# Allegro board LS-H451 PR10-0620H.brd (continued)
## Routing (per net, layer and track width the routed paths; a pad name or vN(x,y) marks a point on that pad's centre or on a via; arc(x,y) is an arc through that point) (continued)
LINE1-L_C: length 8.1
  TOP w0.305: v1(25.06,16.39) 24.98,16.39 24.34,17.02 RA202.1
  IN2 w0.305: v1(25.06,16.39) 21.74,13.06 v1(20.13,13.06)
  BOTTOM w0.305: CA165.2 v1(20.13,13.06)
LINE1-L_R: length 11
  TOP w0.127: RA32.1 24.02,18.04 v3(24.02,18.92)
  TOP w0.305: v1(25.06,17.02) 25.06,17.3 24.51,17.85 RA32.1
  IN2 w0.305: v1(18.93,13.06) 19.65,13.79 21.4,13.79 24.64,17.02 v1(25.06,17.02)
  BOTTOM w0.305: CA166.2 18.89,13.02 v1(18.93,13.06)
LINE1_L: length 2.2
  TOP w0.203: v1(19.23,14.58) 18.99,14.82 UA7.18
  BOTTOM w0.305: CA165.1 20.12,13.79 19.33,14.58 v1(19.23,14.58)
LINE1_R: length 1.8
  TOP w0.203: v1(18.63,14.53) 18.63,14.97 18.59,15.01 UA7.17
  BOTTOM w0.305: CA166.1 18.63,14.04 v1(18.63,14.53)
LX_5VB: length 9.8
  IN2 w0.254: v1(9.34,75.98) 5.78,72.42 5.78,68.87 5.4,68.48 v1(5.4,68.47)
  BOTTOM w0.508: v1(5.4,68.47) 5.91,68.47 5.93,68.5 PR516.1
  vias: v3(8.5,77.22)
MIC_CAP:
  vias: v2(17.66,13.98)
POK: length 1.5
  BOTTOM w0.254: PR511.1 7.88,71.87 7.09,72.66 PU502.12
POWER_SW#_MB: length 60.1
  TOP w0.102: SW3.4 12.45,70.65 11.24,69.44 v1(11.24,67.39)
  IN1 w0.135: v1(11.24,67.39) 10.57,67.39 8,64.83 8,58.54 10.62,55.92 10.62,25.9 11,25.52 11,23.6 11.69,22.91 11.69,20.41 v1(11.51,20.23)
  BOTTOM w0.102: JIO1.7 15.59,19.55 14.86,20.28 14.44,20.28 13.55,19.39 11.57,19.39 11.51,19.45 v1(11.51,20.23)
PWM_FAN1: length 30
  TOP w0.102: v2(14.8,24.2) 14.75,24.25 v1(14.09,24.25)
  IN2 w0.135: v1(11.43,39.44) 12.51,38.36 12.51,25.83 v1(14.09,24.25)
  BOTTOM w0.102: v1(14.09,24.25) 14.23,24.11 15.69,24.11 JIO1.16 ; v1(11.43,39.44) 11.37,39.38 8.45,39.38 8.16,39.66 JFAN1.2 8.16,42.26 9.16,43.26 11.85,43.26 12.46,43.87 C124.1
RING2: length 25.4
  TOP w0.203: UA7.13 16.99,14.96 16.51,14.48 v1(16.51,14.42) v1(16.51,13.84)
  IN1 w1.016: 20.77,15.25 22.33,15.25 23.06,15.98 23.06,17.86 23.64,18.44 23.64,22.72 22.99,23.37 22.99,24.96 25.47,27.44 25.47,33.41 26.48,34.42 26.48,34.93
  vias: v1(27.55,35.31) v1(28.13,35.31)
RING2_R: length 16.4
  IN2 w1.016: JHP1.4 37.5,34.79 35.88,36.4 23.56,36.4
  BOTTOM w0.127: LA27.2 25.17,35.29 25.78,34.68 v2(25.78,34.17)
  vias: v1(20.62,36.58) v1(20.62,35.95)
SLEEVE: length 20.2
  TOP w0.203: UA7.14 17.39,14.82 17.11,14.55 v1(17.11,14.42) v1(17.11,13.84)
  IN1 w1.016: 21.09,13.85 22.55,13.85 24.2,15.5 24.2,17.38 24.78,17.97 24.78,24.66 26.61,26.49 26.61,29.15
  vias: v1(26.74,30.99) v1(26.74,30.3) v2(26.04,30.3)
SLEEVE_R: length 25.9
  IN2 w0.838: JHP1.1 37.5,25.79 36.46,24.75 28.83,24.75 28,25.58
  IN2 w1.016: 28,25.58 25.59,27.98 25.59,32.77 23.56,34.8 20.51,34.8 19.69,35.63
  vias: v1(18.67,36.65) v1(18.67,36.01) v1(18.67,34.74) v1(19.31,34.74) v1(23.37,33.28) v1(23.37,32.65) v3(22.86,33.03)
SPK_-OUT-L+: length 27.2
  TOP w0.203: v1(18.48,23.18) v1(18.48,22.6) 18.19,22.3 UA7.35
  IN1 w0.762: 17.78,21.66 17.09,20.96 14.66,20.96 13.72,20.02 13.72,17.43 11.97,15.68 11.97,10.78 12.26,10.48 12.26,8.18 13.01,7.44 17.28,7.44 18.48,6.23
  vias: v1(18.41,5.47) v1(18.99,5.47)
SPK_-OUT-L-: length 24.8
  TOP w0.203: UA7.36 17.79,21.53 v1(17.09,22.23) v1(17.09,23.37)
  IN1 w0.762: 14.16,21.72 12.83,20.39 12.83,17.8 11.08,16.05 11.08,10.41 11.37,10.12 11.37,7.82 12.64,6.55 16.7,6.55 17.09,6.17
  vias: v1(16.82,5.47) v1(17.4,5.47)
SPK_-OUT-R+: length 22.4
  TOP w0.203: v1(14.3,22.68) v1(14.91,22.68) 15.52,22.68 16.99,21.22 UA7.38
  IN2 w0.762: 13.88,21.7 13.87,21.68 13.87,17.58 11.97,15.68 11.97,10.76 12.26,10.47 12.26,8.18 13.2,7.25 14.42,7.25 15.5,6.17
  vias: v1(14.98,5.47) v1(15.56,5.47)
SPK_-OUT-R-: length 23.9
  TOP w0.203: UA7.37 17.39,21.29 16.41,22.27 v1(16.41,22.89) v1(16.41,23.48)
  IN2 w0.762: 15.31,23.44 13.91,23.44 12.98,22.51 12.98,17.95 11.08,16.05 11.08,10.39 11.37,10.1 11.37,7.82 12.89,6.29 13.02,6.29
  vias: v1(13.33,5.47) v1(13.91,5.47)
SPK_L+:
  vias: v1(18.93,8.97) v1(18.93,8.38)
SPK_L-:
  vias: v1(16.77,9.04) v1(16.77,8.46)
SPK_R+:
  vias: v1(15.5,9.04) v1(15.5,8.46)
SPK_R-:
  vias: v1(13.3,9.03) v1(13.3,8.45)
SPKR: length 26.1
  TOP w0.102: DA19.2 6.51,15.32 10.59,11.24 v2(10.59,10.42) v1(10.59,9.62)
  IN1 w0.135: v1(10.59,9.62) 10.25,9.97 10.25,15.72 9.93,16.05 9.93,16.72 10.93,17.72 10.93,19.06 10.23,19.75 10.23,20.79 v1(11.15,21.72)
  BOTTOM w0.102: v1(11.15,21.72) 11.2,21.72 11.67,21.24 11.67,21.11 11.78,21.01 14.26,21.01 14.38,20.89 15.13,20.89 15.46,20.55 JIO1.9
TACH_FAN1: length 26.3
  TOP w0.102: v1(9.16,39.82) 9.99,40.65 v1(11.5,40.65) ; v2(15.75,25.03) 15.62,24.89 v1(14.09,24.89)
  IN2 w0.135: v1(14.09,24.89) 13.21,25.77 13.21,38.93 v1(11.5,40.65)
  BOTTOM w0.102: v1(14.09,24.89) 14.47,24.51 14.47,24.45 14.57,24.34 15.29,24.34 15.49,24.55 JIO1.17 ; v1(11.5,40.65) 12.67,40.65 CE99.1 12.77,40.8 C123.1 ; JFAN1.3 v1(9.16,39.82)
USB3_CRX_DTX_N3: length 60.4
  TOP w0.102: v1(21.47,68.46) 21.28,68.27 20.96,68.27 20.65,67.96 20.65,66.25 22.86,64.04 22.86,63.74 22.68,63.55 22.31,63.55 22.18,63.68 EU1.9 EU1.1 20.54,63.68 20.41,63.55 18.33,63.55 v4(17.98,63.9) 17.64,64.24 14.91,64.24 v1(14.73,64.42)
  IN1 w0.135: v1(13.78,31.63) 13.65,31.5 12.95,31.5 12.28,32.17 12.28,38.34 13.02,39.08 13.02,41.73 12.28,42.47 12.28,60.23 15.56,63.51 15.56,64.01 15.25,64.33 14.83,64.33 v1(14.73,64.42)
  IN2 w0.135: v1(21.47,68.46) 21.59,68.33 25.91,68.33 26.59,69.01 27.05,69.01 27.18,69.15 JUSB1.5
  BOTTOM w0.102: JIO1.31 15.75,31.55 15.7,31.5 15.4,31.5 15.35,31.55 14.44,31.55 14.32,31.44 13.98,31.44 v1(13.78,31.63)
USB3_CRX_DTX_N4: length 33.1
  TOP w0.102: v1(13.66,45.56) 13.82,45.39 18.82,45.39 18.95,45.52 EU8.1 EU8.9 20.59,45.52 20.72,45.39 20.89,45.39 20.99,45.49 20.99,46.46 20.65,46.8 20.65,49.1 21.01,49.46 21.33,49.46 v1(21.47,49.6)
  IN1 w0.135: v1(13.66,45.56) 13.79,45.43 14.08,45.43 14.48,45.03 14.48,42.55 14.61,42.42 14.61,38.52 13.8,37.71 13.8,34.8 13.99,34.61 14.16,34.61 v1(14.29,34.74)
  IN2 w0.135: JUSB2.5 27.18,49.6 27.05,49.46 26.54,49.46 25.98,48.9 24.77,48.9 24.2,49.47 21.59,49.47 v1(21.47,49.6)
  BOTTOM w0.102: v1(14.29,34.74) 14.48,34.55 JIO1.37
USB3_CRX_DTX_P3: length 60.5
  TOP w0.102: v1(21.47,67.87) 21.32,68.02 21.06,68.02 20.9,67.86 20.9,66.35 23.1,64.14 23.1,63.63 22.78,63.31 22.28,63.31 22.16,63.18 EU1.8 EU1.2 20.54,63.18 20.41,63.31 18.22,63.31 17.53,64 14.89,64 v1(14.73,63.84)
  IN1 w0.135: v1(14.73,63.84) 14.9,64 15.12,64 15.24,63.88 15.24,63.64 11.96,60.36 11.96,42.33 12.7,41.59 12.7,39.21 11.96,38.47 11.96,32.04 12.82,31.18 13.65,31.18 v1(13.78,31.05)
  IN2 w0.135: JUSB1.6 27.18,68.55 27.05,68.69 26.72,68.69 26.05,68.01 21.6,68.01 v1(21.47,67.87)
  BOTTOM w0.102: JIO1.30 15.62,31.18 15.37,31.18 15.25,31.3 14.54,31.3 14.43,31.19 13.93,31.19 v1(13.78,31.05)
USB3_CRX_DTX_P4: length 33.3
  TOP w0.102: v1(21.47,49.02) 21.26,49.22 21.12,49.22 20.9,49 20.9,46.9 21.24,46.56 21.24,45.39 20.99,45.15 20.7,45.15 20.57,45.02 EU8.8 EU8.2 18.95,45.02 18.82,45.15 13.82,45.15 v1(13.66,44.98)
  IN1 w0.135: v1(13.66,44.98) 13.79,45.11 13.94,45.11 14.16,44.89 14.16,42.42 14.29,42.29 14.29,38.65 13.48,37.84 13.48,34.66 13.86,34.29 14.16,34.29 v1(14.29,34.16)
  IN2 w0.135: v1(21.47,49.02) 21.6,49.15 24.06,49.15 24.63,48.58 26.11,48.58 26.67,49.14 27.05,49.14 27.18,49 JUSB2.6
  BOTTOM w0.102: v1(14.29,34.16) 14.44,34.3 15.3,34.3 15.55,34.05 JIO1.36
USB3_CTX_C_DRX_N3: length 12.2
  TOP w0.102: CI143.2 17.75,62.05 v4(18.58,62.05) 20.41,62.05 20.54,62.18 EU1.4 EU1.7 22.4,62.18 22.52,62.05 22.88,62.05 v1(23.05,62.22)
  IN2 w0.135: JUSB1.8 27.18,63.17 27.03,63.02 26.86,63.02 26.03,63.85 24.44,63.85 23.54,62.95 23.54,62.22 23.38,62.05 23.22,62.05 v1(23.05,62.22)
USB3_CTX_C_DRX_N4: length 11
  TOP w0.102: CI141.2 17.92,43.85 18.4,43.85 18.45,43.89 18.82,43.89 18.95,44.02 EU8.4 EU8.7 20.89,44.02 21.01,43.89 21.28,43.89 v1(21.47,44.08)
  IN2 w0.135: v1(21.47,44.08) 21.6,43.94 22.3,43.94 22.5,44.14 26.18,44.14 26.87,43.46 27.05,43.46 27.18,43.6 JUSB2.8
USB3_CTX_C_DRX_P3: length 12.2
  TOP w0.102: v1(23.05,61.64) 22.88,61.81 22.52,61.81 22.4,61.68 EU1.6 EU1.5 20.54,61.68 20.41,61.81 v4(19.96,61.81) 17.84,61.81 CI142.2
  IN2 w0.135: JUSB1.9 27.18,62.58 27.06,62.7 26.73,62.7 25.9,63.53 24.58,63.53 23.87,62.82 23.87,62.08 23.51,61.73 23.14,61.73 v1(23.05,61.64)
USB3_CTX_C_DRX_P4: length 10.9
  TOP w0.102: CI140.2 17.92,43.6 18.51,43.6 18.55,43.65 18.82,43.65 18.95,43.52 EU8.5 EU8.6 20.91,43.52 21.04,43.65 21.31,43.65 v1(21.47,43.49)
  IN2 w0.135: JUSB2.9 27.18,43 27.05,43.14 26.73,43.14 26.05,43.82 22.63,43.82 22.43,43.62 21.6,43.62 v1(21.47,43.49)
USB3_CTX_DRX_N3: length 36.7
  TOP w0.102: v1(15.29,62.18) 15.46,62.01 16.76,62.01 CI143.1
  IN1 w0.135: v1(15.29,62.18) 15.42,62.05 15.94,62.05 16.26,61.73 16.26,61.09 13.04,57.88 13.04,42.85 13.79,42.1 13.79,38.77 13.04,38.02 13.04,33.08 13.29,32.83 13.65,32.83 v1(13.78,32.96)
  BOTTOM w0.102: v1(13.78,32.96) 13.95,32.8 15.14,32.8 15.39,33.05 JIO1.34
USB3_CTX_DRX_N4: length 12.8
  TOP w0.102: v1(14.99,44.01) 15.15,43.85 16.88,43.85 CI141.1
  IN1 w0.135: v1(14.99,44.01) 15.12,43.88 15.51,43.88 15.94,43.45 15.94,38.77 14.57,37.39 14.57,36.13 14.69,36.01 14.8,36.01 v1(14.99,36.2)
  BOTTOM w0.102: JIO1.40 15.64,35.94 15.25,35.94 v1(14.99,36.2)
USB3_CTX_DRX_P3: length 36.5
  TOP w0.102: CI142.1 16.76,61.76 15.46,61.76 v1(15.29,61.59)
  IN1 w0.135: v1(15.29,61.59) 15.42,61.73 15.81,61.73 15.94,61.59 15.94,61.23 12.72,58.01 12.72,42.71 13.47,41.97 13.47,38.9 12.72,38.16 12.72,32.95 13.16,32.51 13.65,32.51 v1(13.78,32.38)
  BOTTOM w0.102: JIO1.33 13.95,32.55 v1(13.78,32.38)
USB3_CTX_DRX_P4: length 12.8
  TOP w0.102: CI140.1 16.88,43.6 15.16,43.6 v1(14.99,43.43)
  IN1 w0.135: v1(14.99,43.43) 15.12,43.56 15.37,43.56 15.62,43.31 15.62,38.9 14.24,37.53 14.24,35.99 14.55,35.68 14.8,35.68 v1(14.99,35.49)
  BOTTOM w0.102: JIO1.39 15.75,35.55 15.6,35.69 15.19,35.69 v1(14.99,35.49)
USB20_N1_R: length 47.9
  IN1 w0.104: v1(14.42,66.54) 14.61,66.35 14.61,65.56 11.34,62.29 11.34,41.99 11.94,41.39 11.94,39.33 11.34,38.73 11.34,28.28 14.01,25.61 14.8,25.61 v1(14.9,25.51)
  BOTTOM w0.094: JIO1.19 15.75,25.55 15.66,25.63 15.03,25.63 v1(14.9,25.51) ; v1(14.42,66.54) 14.42,65.92 14.79,65.55 LU1.3
USB20_N1_R1: length 11.7
  IN2 w0.104: JUSB1.2 25.68,65.65 25.58,65.75 19.35,65.75 v1(19.12,65.53)
  BOTTOM w0.094: v1(19.12,65.53) 18.92,65.73 18.26,65.73 18.2,65.67 DI1.2 17.36,65.74 16.9,65.74 16.63,65.47 RU1.2
USB20_N2_R: length 24.5
  IN1 w0.104: v1(16.49,27.26) 16.31,27.44 16.05,27.44 15.56,27.93 15.56,37.17 16.45,38.06 16.45,46.28 15.64,47.09 14.62,47.09 v1(14.43,46.89)
  BOTTOM w0.094: JIO1.22 15.88,27.05 16.2,27.37 16.38,27.37 v1(16.49,27.26) ; v1(14.43,46.89) 14.63,47.09 15.06,47.09 15.22,46.94 LU2.3
USB20_N2_R1: length 13
  IN2 w0.104: v1(21.5,47.82) 21.69,48.01 22.26,48.01 24.08,46.2 25.58,46.2 25.68,46.1 JUSB2.2
  BOTTOM w0.094: v1(21.5,47.82) 21.3,48.02 19.51,48.02 18.64,47.16 18.26,47.16 18.2,47.1 DI2.2 17.39,47.1 16.67,47.1 16.44,46.87 RU4.2
USB20_P1_R: length 47.9
  IN1 w0.104: v1(14.9,26.09) 14.61,25.8 14.09,25.8 12.7,27.19 12.7,27.21 12.66,27.26 12.64,27.26 11.53,28.36 11.53,38.65 12.13,39.25 12.13,41.47 11.53,42.07 11.53,62.21 14.8,65.48 14.8,66.35 v1(15,66.54)
  BOTTOM w0.094: JIO1.20 15.75,26.05 15.57,26.05 15.34,25.82 15.18,25.82 v1(14.9,26.09) ; v1(15,66.54) 14.6,66.14 14.6,66 14.87,65.73 15.18,65.73 15.24,65.79 15.24,65.98 15.31,66.05 LU1.2
USB20_P1_R1: length 11.7
  IN2 w0.104: JUSB1.3 25.68,66.05 25.58,65.95 19.28,65.95 v1(19.12,66.11)
  BOTTOM w0.094: RU2.2 16.6,66.11 16.79,65.92 17.3,65.92 DI1.3 18.2,66.04 18.33,65.91 18.92,65.91 v1(19.12,66.11)
USB20_P2_R: length 24.5
  IN1 w0.104: v1(14.43,47.48) 14.62,47.28 15.72,47.28 16.64,46.36 16.64,37.98 15.75,37.09 15.75,28.01 16.13,27.63 16.28,27.63 v1(16.49,27.84)
  BOTTOM w0.094: JIO1.23 16.2,27.55 v1(16.49,27.84) ; LU2.2 15.22,47.44 15.06,47.28 14.63,47.28 v1(14.43,47.48)
USB20_P2_R1: length 13
  IN2 w0.104: JUSB2.3 25.68,46.5 25.58,46.4 24.16,46.4 22.34,48.21 21.69,48.21 v1(21.5,48.4)
  BOTTOM w0.094: RU3.2 16.44,47.5 16.67,47.28 17.27,47.28 DI2.3 18.2,47.43 18.29,47.34 18.57,47.34 19.43,48.2 21.3,48.2 v1(21.5,48.4)
USB_EN#: length 49.9
  TOP w0.102: v2(6.04,62.31) 6.43,62.71 v1(6.67,62.71)
  IN1 w0.135: v1(10.62,22.79) 10.48,22.93 10.48,25.28 10.1,25.66 10.1,55.63 7.48,58.25 7.48,60.6 6.25,61.83 6.25,62.29 v1(6.67,62.71)
  BOTTOM w0.102: JIO1.10 15.29,21.05 15.22,21.11 14.48,21.11 14.35,21.24 11.98,21.24 11.88,21.33 11.88,21.35 11.56,21.68 11.56,22.21 11.37,22.4 11.04,22.4 10.64,22.79 v1(10.62,22.79) ; UU1.4 6.42,62.96 v1(6.67,62.71)
USB_OC0#: length 48.1
  TOP w0.102: v1(11.2,22.8) 11.27,22.87 v2(11.91,22.87)
  IN1 w0.135: v1(11.2,22.8) 10.74,23.26 10.74,25.4 10.36,25.78 10.36,55.81 7.74,58.43 7.74,60.94 v1(6.67,62)
  BOTTOM w0.102: UU1.3 6.42,61.75 v1(6.67,62) ; JIO1.11 15.49,21.55 15.28,21.34 14.57,21.34 13.68,22.23 12.56,22.23 12.38,22.05 12.04,22.05 11.29,22.8 v1(11.2,22.8)
N70870692: length 1.2
  BOTTOM w0.305: RA200.1 23.44,18.45 DA18.2
N70870708: length 1.1
  BOTTOM w0.305: DA18.3 24.13,19.1 RA33.1
N70876967: length 3.5
  TOP w0.102: v2(10.05,14.31) RA9.2 11.52,13.9 RV30.1 12.39,14.28 12.46,14.28 12.47,14.29 CA14.1
N70877136: length 1.7
  TOP w0.102: UA7.10 15.42,16.22 14.57,16.22 14.23,15.88 RA209.2
N70877951: length 1.2
  TOP w0.102: RA225.1 v2(8.12,61.23)
N70878061: length 5.5
  TOP w0.102: v2(8.74,57.32) RA122.2 RA511.1 CA999.1 8.74,54.32 v1(8.77,54.3) 8.74,54.27 8.74,53.94 8.81,53.87 UA2.5 ; UA2.3 9.61,54.25 v1(9.66,54.3)
  BOTTOM w0.102: v1(8.77,54.3) v1(9.66,54.3)
N70878070: length 1.4
  TOP w0.102: UA2.12 9.61,51.04 9.66,51 9.66,50.34 CA144.1
N70878091: length 1.4
  TOP w0.102: UA2.10 8.81,50.98 8.77,50.93 8.77,50.4 CA145.1
N71020818:
  vias: v1(1.45,63.99) v1(1.45,63.4) v1(1.45,62.82) v1(1.45,62.24) v1(2.67,73.31) v1(2.67,72.73) v1(2.67,72.14) v1(2.67,71.56) v3(1.59,69.56)
N71020841: length 1.5
  BOTTOM w0.254: PU502.11 7.59,72.85 8.45,71.99 PR513.2
N71020850: length 2.8
  BOTTOM w0.254: PU502.16 4.03,73.02 3.69,72.68 v2(3.69,72.36) 3.69,71.55 PR512.2
N71020923: length 1.4
  BOTTOM w0.254: PR517.1 6.16,70.68 PC530.1 6.04,69.96 PR516.2
N71020937: length 2.5
  BOTTOM w0.254: PU502.14 6.09,72.6 5.41,71.93 4.92,71.93 4.58,71.58 PR515.1
N71020947: length 11.7
  IN1 w0.254: v1(4.58,77.44) 4.58,73.42 v1(7.51,70.49)
  BOTTOM w0.102: v2(4.07,77.53) 4.16,77.44 v1(4.58,77.44)
  BOTTOM w0.254: v1(7.51,70.49) 7.88,70.86 PR511.2 ; v1(4.58,77.44) PC528.1 5.24,76.99 5.09,76.83 PU502.3

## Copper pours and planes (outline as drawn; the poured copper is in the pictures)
+3V_DVDD on TOP: 13.18,22.45 13.12,22.39 11.56,22.39 11.44,22.51 11.44,23.11 10.99,23.56 10.99,26.42 11.05,26.49 12.96,26.49 13.02,26.42 13.02,23.66 13.18,23.5
+3VALW on TOP: 8.51,53.16 6.54,53.16 6.42,53.28 6.42,54.74 6.54,54.87 8.32,54.87 8.39,54.81 8.39,54.04 8.51,53.92
+3VS_AUDIO on TOP (solid shape): 8.51,49 8.51,46.67 8.3,46.46 7.6,46.46 7.39,46.67 7.39,48.96 7.45,49.02 8.48,49.02
+3VS_AUDIO_R on TOP (solid shape): 8.53,51.82 8.53,49.74 8.45,49.66 7.53,49.66 7.46,49.73 7.46,51.77 7.58,51.89 8.46,51.89
+5V_AVDD on TOP: 19.72,15.96 20,15.96 21.47,14.49 21.47,14.48 21.85,14.1 21.85,14.1 22.43,14.1 22.89,13.64 22.89,13.29 22.95,13.23 23.52,13.23 23.65,13.11 23.65,12.42 23.74,12.33 24.39,12.33 24.45,12.26 24.45,11.12 24.39,11.06 20.96,11.06 20.7,11.31 20.7,14.48 20.15,15.03 19.73,15.03 19.67,15.08 19.67,15.92
+5VALW on BOTTOM (solid shape): 10.99,64.48 11.69,64.48 11.69,64.99 12.19,64.99 12.19,64.48 12.89,64.48 12.89,64.99 13.53,64.99 13.72,64.8 13.72,63.21 13.53,63.02 8.26,63.02 8,63.28 8,64.86 8.13,64.99 10.99,64.99
+5VALW on TOP: 9.15,53.16 9.08,53.22 9.08,57.47 9.53,57.92 9.53,60.59 7.62,62.49 7.62,67.19 7.94,67.51 10.29,67.51 10.42,67.38 10.42,63.82 12.61,61.63 12.61,53.45 12.32,53.16
+5VALWBP on BOTTOM (solid shape): 16.39,73.16 16.39,67.7 16.32,67.63 13.71,67.63 13.55,67.48 13.55,65.35 13.36,65.16 8.44,65.16 8.13,65.47 8.13,67.39 10.89,67.39 10.89,67.34 10.9,67.29 10.92,67.24 10.95,67.19 10.98,67.15 11.02,67.11 11.06,67.08 11.11,67.06 11.16,67.04 11.22,67.04 11.27,67.04 11.32,67.04 11.37,67.06 11.42,67.08 11.47,67.11 11.5,67.15 11.54,67.19 11.56,67.24 11.58,67.29 11.6,67.34 11.6,67.39 11.6,67.45 11.58,67.5 11.56,67.55 11.54,67.59 11.5,67.64 11.47,67.67 11.42,67.7 11.37,67.72 11.32,67.74 11.27,67.75 11.22,67.75 11.16,67.74 11.11,67.72 11.06,67.7 11.02,67.67 10.98,67.64 10.95,67.59 10.92,67.55 10.9,67.5 10.89,67.45 10.89,67.39 8.13,67.39 8.13,70.11 8.15,70.13 9.94,70.13 10,70.19 10.3,70.19 11.18,71.07 11.18,73.2 11.4,73.41 16.13,73.41
+5VS_AUDIO on TOP: 15.44,20.55 15.4,20.59 15.4,21.15 14.27,21.15 13.78,21.64 13.54,21.64 13.36,21.83 13.36,23.43 13.76,23.83 13.76,24.93 14.12,25.28 14.12,38.71 9.08,43.74 9.08,48.67 9.5,49.08 11.77,49.08 12.23,48.63 12.23,45.51 17.54,40.2 17.54,28.82 18.96,27.4 18.96,24.1 19.69,23.38 19.69,22.36 18.74,21.41 18.74,20.2 18.67,20.14 16.51,20.14 16.39,20.26 16.39,20.55
+5VS_AUDIO on TOP: 22.95,10.54 24.41,10.54 24.49,10.46 24.49,9.39 24.43,9.33 22.28,9.33 21.5,8.54 20.49,8.54 20.44,8.59 20.44,10.03 20.51,10.09 21.45,10.09 21.73,10.37 22.79,10.37
+5VS_AUDIO on IN1: 6.54,3.82 4.96,5.4 4.96,25.79 6.04,26.87 6.04,48.27 6.86,49.09 9.72,49.09 9.85,48.96 9.85,25.41 8.42,23.98 8.42,7.75 11.15,5.02 19.12,5.02 19.43,5.34 19.43,9.4 20.37,10.34 21.06,10.34 21.21,10.48 22.67,10.48 22.67,6.1 20.39,3.82
+5VS_AUDIO on IN2: 6.54,3.82 4.96,5.4 4.96,7.5 8.67,7.5 11.15,5.02 19.12,5.02 19.43,5.34 19.43,9.4 20.36,10.33 21.07,10.33 21.23,10.48 22.67,10.48 22.67,6.1 20.39,3.82
+5VS_AUDIO on IN2: 15.68,26.79 20.01,26.79 20.25,26.55 20.25,23.48 18.92,22.15 17.07,22.15 16.85,22.37 16.85,23.83 16.59,24.1 15.84,24.1 15.35,24.59 15.35,26.46
+5VS_AUDIO_R on TOP (solid shape): 11.08,51.74 11.08,49.71 11.01,49.64 10.03,49.64 9.87,49.8 9.87,51.82 9.95,51.89 10.93,51.89
+5VS_FAN on BOTTOM (solid shape): 12.94,43.47 12.94,41.84 12.79,41.69 12.28,41.69 11.75,41.15 11.28,41.15 11.11,40.98 11.08,40.99 10.74,40.9 10.64,40.55 10.65,40.53 10.28,40.16 9.95,40.16 9.8,40.31 9.8,41.71 9.39,42.13 9.39,42.65 9.54,42.81 11.65,42.81 12.34,43.49 12.92,43.49
AGND on TOP (solid shape): 20.58,11.26 20.63,11.21 20.64,11.15 20.59,11.12 20.34,10.87 19.63,10.87 19.38,11.12 18.01,11.12 17.91,11.18 17.94,11.29 18.19,11.55 18.32,11.55 18.32,11.94 20.58,11.94
AGND on TOP (solid shape): 15.57,12.52 16.57,12.52 16.58,12.53 16.64,12.5 16.64,12.45 18.28,12.45 18.29,12.46 18.35,12.44 18.35,12.31 16.68,12.31 16.68,11.55 16.69,11.55 16.71,11.49 16.6,11.37 16.58,11.37 16.51,11.31 14.41,11.31 14.32,11.35 14.31,11.44 14.33,11.56 14.31,11.67 14.33,11.76 14.41,11.8 15.41,11.8 15.41,12.58 15.51,12.58
AGND on TOP (solid shape): outline of 1217 points within 18.87,11.12 38.84,37.09
AGND on BOTTOM (solid shape): 21.28,27.37 21.28,26.99 21.44,26.83 21.5,26.83 21.56,26.84 21.68,26.83 21.79,26.85 21.92,26.85 22.05,26.73 22.05,25.25 22.04,25.25 22.04,24.9 21.85,24.9 21.85,23.63 21.61,23.63 21.09,23.77 21.02,23.24 21.02,22.36 22.04,22.36 22.04,21.53 21.11,21.53 19.9,20.33 18.99,20.33 18.99,21.49 20.77,23.27 20.77,27.31 20.9,27.44 21.21,27.44
AGND on BOTTOM (solid shape): 25.59,32.06 25.58,32.05 25.58,31.83 25.57,31.82 25.57,31.13 25.58,31.12 25.58,30.19 25.99,29.79 26.86,29.79 26.95,29.72 26.93,29.61 24.62,27.3 24.62,24.26 23.69,24.26 23.69,28.99 24.02,29.2 23.95,29.59 23.92,29.66 23.95,29.74 24.01,30.2 23.56,30.33 23.55,30.32 23.39,30.32 23.39,30.39 22.98,30.39 22.98,30.32 22.93,30.32 22.93,30.85 23.09,31.15 22.93,31.45 22.93,31.67 23.09,31.81 23.14,32.03 23.17,32.1 23.24,32.14 25.59,32.14
AGND on BOTTOM: 19.61,10.87 19.35,11.12 18.9,11.12 18.25,11.77 18.25,15.75 19.73,15.75 20.13,16.16 20.13,18.19 20.24,18.29 21.21,18.29 21.21,16.89 21.18,16.7 21.24,16.52 21.25,16.51 21.25,16.46 22.05,15.66 23.87,15.66 24.28,16.07 24.9,16.07 25.35,16.18 25.32,16.64 25.29,16.71 25.32,16.78 25.41,17.12 25.15,17.37 25.08,17.44 25.11,17.54 25.18,17.61 25.18,27.07 27.84,29.74 27.84,32.04 27.27,32.61 27.27,32.98 27.14,32.98 27.14,33.66 28.31,33.66 28.33,33.25 28.57,32.92 28.67,32.86 28.79,32.81 28.79,27.76 28.29,26.99 28.99,26.38 30.79,26.38 30.79,26.19 30.98,25.72 31.44,25.53 31.9,25.72 32.09,26.19 32.09,26.38 38.84,26.38 38.84,24 37.98,24 26.8,24 25.95,23.65 25.6,22.8 25.6,11.12 21.11,11.12 20.85,10.87
AGND on GND1: 19.6,10.86 19.35,11.12 13.06,11.12 12.96,11.22 12.96,14.63 13.06,14.74 14.97,14.74 15.98,15.75 19.73,15.75 20.13,16.16 20.13,18.19 20.24,18.29 22.59,18.29 23.05,18.76 23.05,21.19 22.71,21.53 21.11,21.53 19.9,20.33 18.99,20.33 18.99,21.49 20.77,23.27 20.77,33.51 20.24,34.04 18.27,34.04 18.16,34.15 18.16,36.86 18.4,37.09 37.87,37.09 37.87,36.1 38.84,36.1 38.84,34.19 33.54,34.19 33.54,34.69 32.64,35.59 31.74,34.69 31.74,34.19 28.99,34.19 28.3,33.59 28.79,32.82 28.79,27.76 28.3,26.99 28.99,26.39 30.79,26.39 30.79,26.19 31.44,25.53 32.09,26.19 32.09,26.39 38.84,26.39 38.84,24 26.8,24 25.95,23.65 25.6,22.8 25.6,11.12 21.11,11.12 20.85,10.86
AGND on GND2: 19.6,10.86 19.35,11.12 18.9,11.12 18.08,11.94 13.25,11.94 12.96,12.24 12.96,14.63 13.06,14.74 14.97,14.74 15.98,15.75 19.73,15.75 20.13,16.16 20.13,18.19 20.24,18.29 22.59,18.29 23.05,18.76 23.05,21.19 22.71,21.53 21.11,21.53 19.9,20.33 18.99,20.33 18.99,21.49 20.77,23.27 20.77,33.51 20.24,34.04 18.27,34.04 18.16,34.15 18.16,36.86 18.4,37.09 37.87,37.09 37.87,36.1 38.84,36.1 38.84,34.19 33.54,34.19 33.54,34.69 32.64,35.59 31.74,34.69 31.74,34.19 28.99,34.19 28.3,33.59 28.79,32.82 28.79,27.76 28.3,26.99 28.99,26.39 30.79,26.39 30.79,26.19 31.44,25.53 32.09,26.19 32.09,26.39 38.84,26.39 38.84,24 26.8,24 25.95,23.65 25.6,22.8 25.6,11.12 21.11,11.12 20.85,10.86
GND on TOP (solid shape): 32,72.85 31.2,72.85 31.2,75.1 24.6,75.1 24.6,37.05 31.2,37.05 31.2,39.3 32,39.3 32,36.25 23.8,36.25 23.8,75.9 32,75.9
GND on TOP (solid shape): 17.67,33.68 17.73,33.77 17.85,33.75 18.06,33.53 20.03,33.53 20.26,33.3 20.26,23.48 20.11,23.33 19.86,23.33 19.09,24.1 19.09,27.45 17.67,28.87
GND on TOP (solid shape): outline of 4085 points within 0.2,0.2 37.87,83.8
GND on BOTTOM (solid shape): 31.8,75.1 24.6,75.1 24.6,37.05 31.8,37.05 31.8,36.25 23.8,36.25 23.8,75.9 31.8,75.9
GND on BOTTOM (solid shape): 5.64,70.71 5.64,70.05 5.46,69.88 5.46,69.12 4.64,68.29 3.62,68.29 3.62,70.83 3.69,70.9 5.45,70.9
GND on BOTTOM (solid shape): 6.1,67.93 6.1,65.18 6.08,65.17 6.08,65.12 3.94,65.12 3.62,65.44 3.62,67.85 3.75,67.98 6.06,67.98
GND on BOTTOM (solid shape): 7.88,69.63 7.88,64.36 7.81,64.29 6.63,64.29 6.48,64.44 6.48,69.56 6.67,69.75 7.75,69.75
GND on BOTTOM (solid shape): 6.09,12.45 6.09,8.95 5.81,8.67 3.57,8.67 3.31,8.93 3.31,11.73 4.26,12.67 5.87,12.67
GND on BOTTOM (solid shape): 27.27,72.05 27.42,71.66 27.78,71.42 27.78,71.25 25.09,71.25 25.09,72.05
GND on BOTTOM (solid shape): 27.27,52.5 27.42,52.11 27.78,51.87 27.78,51.7 25.09,51.7 25.09,52.5
GND on BOTTOM (solid shape): 27.78,60.28 27.42,60.04 27.27,59.65 25.09,59.65 25.09,60.45 27.78,60.45
GND on BOTTOM (solid shape): 27.78,40.73 27.42,40.49 27.27,40.1 25.09,40.1 25.09,40.9 27.78,40.9
GND on BOTTOM (solid shape): 5.18,79.2 6.2,78.5 7.41,78.19 7.69,77.91 7.69,76.93 7.31,76.55 7.31,75.28 6.93,74.9 1.53,74.9 1.46,74.96 1.46,77.12 1.59,77.25 4.19,77.25 4.7,76.74 4.7,75.66 4.89,75.47 5.21,75.47 5.4,75.66 5.4,76.55 5.78,76.93 5.78,77.88 5.66,78.01 4.77,78.01 4.51,78.26 4.51,78.96 4.75,79.2
GND on BOTTOM (solid shape): 16.68,23.24 16.72,23.26 16.76,23.23 16.95,23.05 17.21,23.04 17.31,23.03 17.35,22.95 17.35,22.66 17.31,22.58 17.21,22.57 16.73,22.23 17.21,21.9 17.31,21.89 17.35,21.8 17.35,16.26 17.34,16.26 17.34,14.93 17.21,14.8 16.07,14.8 15.88,14.61 15.88,13.72 15.76,13.6 13.95,13.6 13.95,13.6 13.91,13.6 13.85,13.53 13.85,13.02 13.78,12.96 10.7,12.96 10.7,16.15 10.7,16.24 10.69,16.32 10.71,16.41 10.79,16.45 12.9,16.45 13.58,15.78 14.27,15.78 14.56,16.07 15.48,16.07 15.67,16.27 15.9,16.27 16.16,16.43 16.11,16.73 16.09,16.8 16.18,17.05 16.09,17.3 16.18,17.55 16.09,17.8 16.18,18.05 16.09,18.3 16.18,18.55 16.09,18.8 16.18,19.05 16.09,19.3 16.18,19.55 16.09,19.8 16.18,20.05 16.09,20.3 16.18,20.55 16.09,20.8 16.18,21.05 16.09,21.3 16.18,21.55 16.09,21.8 16.18,22.05 16.09,22.3 16.11,22.37 16.15,22.42 16.17,22.48 16.22,22.54 16.3,22.55 16.71,22.71 16.65,23.15 16.64,23.18 16.65,23.22
GND on BOTTOM (solid shape): outline of 4389 points within 0.2,0.2 37.87,83.8
GND on IN1 (solid shape): 27.49,60.23 27.49,60.11 27.32,59.34 27.97,58.9 37.87,58.9 37.87,53.25 27.97,53.25 27.28,52.67 27.74,51.88 27.78,51.87 27.78,51.25 19.88,51.25 18.04,53.09 18.04,59.76 18.83,60.55 27.17,60.55
GND on IN1 (solid shape): outline of 615 points within 0.2,0.2 37.87,83.8
GND on IN2 (solid shape): 37.87,53.25 27.97,53.25 27.28,52.67 27.74,51.88 27.78,51.87 27.78,51.25 20.58,51.25 20.58,53.73 19.05,55.25 19.05,57.58 19.7,58.22 25.53,58.22 26.2,58.9 37.87,58.9
GND on IN2 (solid shape): outline of 594 points within 0.2,0.2 37.87,83.8
GND on BOTTOM: 18.29,33.53 20.01,33.53 20.26,33.28 20.26,23.5 20.01,23.25 19.82,23.25 19.05,24.01 19.05,27.44 18.23,28.26 18.23,33.47
GND on BOTTOM: 18.29,18.87 19.43,18.87 19.63,18.68 19.63,16.39 19.5,16.26 18.29,16.26 18.23,16.33 18.23,18.8
GND on GND1: outline of 83 points within 0.2,0.2 37.87,83.8
GND on GND2: outline of 85 points within 0.2,0.2 37.87,83.8
V3D3_STB on TOP: 18.1,15.94 18.23,15.94 18.29,15.88 18.29,12.64 18.23,12.58 16.77,12.58 16.77,13.15 17.72,13.15 18.04,13.47 18.04,15.88
+USB3_VCC on BOTTOM (solid shape): outline of 156 points within 7.81,58.6 21.22,64.17
+USB3_VCC on BOTTOM: 19.17,44.14 20.9,44.14 21.02,44.01 21.02,42.81 21.47,42.36 21.47,41.47 21.34,41.34 18.48,41.34 18.29,41.54 18.29,43.26
+USB3_VCC on IN2: 17.03,40.01 16.85,40.2 16.85,52.29 15.37,53.77 15.37,59.82 14.86,60.33 8.77,60.33 7.81,61.28 7.81,64.2 8,64.4 17.93,64.4 20.81,61.52 23.05,61.52 24.45,62.92 25.89,62.92 26.29,62.52 26.29,59.48 25.45,58.63 19.33,58.63 18.55,57.84 18.55,54.81 20.01,53.35 20.01,44.14 21.06,43.08 22.51,43.08 22.8,43.38 25.85,43.38 26.29,42.93 26.29,41.6 25.29,40.6 24.7,40.01
AUD_HP1_JACK_L on TOP: 20.09,17.97 20.91,17.97 21.01,17.87 21.82,17.87 22.01,17.68 22.26,17.68 22.61,17.33 23.56,17.33 23.6,17.29 23.6,16.75 23.54,16.69 22.68,16.69 22.31,17.06 22.17,17.06 21.81,17.42 21.35,17.42 21.13,17.64 20.97,17.64 20.89,17.72 20.08,17.72 20.07,17.74 20.07,17.94
AUD_HP1_JACK_R on TOP: 20.11,18.35 23.33,18.35 23.33,18.35 23.53,18.35 23.63,18.25 23.63,17.6 23.58,17.55 22.6,17.55 22.33,17.81 22.06,17.81 21.83,18.04 21.04,18.04 20.96,18.12 20.12,18.12 20.08,18.16 20.08,18.32
AUD_SENSE_A on TOP: 13.02,13.79 14.93,13.79 16.1,14.96 16.29,14.96 16.45,15.12 16.45,15.88 16.51,15.94 16.7,15.94 16.7,14.99 16.29,14.58 16.29,14.33 15.37,13.4 15.37,12.83 15.31,12.77 13.02,12.77 12.96,12.83 12.96,13.72
AUD_VREF on TOP: 20.1,16.77 20.94,16.77 21.03,16.69 22.11,16.69 22.32,16.48 23.1,16.48 23.12,16.46 23.12,15.59 23.07,15.53 21.91,15.53 20.93,16.51 20.12,16.51 20.09,16.54 20.09,16.77
B+ on BOTTOM (solid shape): 5.66,64.55 5.66,59.72 5.46,59.53 4,59.53 3.81,59.72 3.81,64.8 3.88,64.86 5.34,64.86
B+ on BOTTOM: 6.8,9.59 6.48,9.91 6.48,12.52 6.67,12.71 9.27,12.71 9.27,9.59
B+ on IN2: 9.97,29.32 9.97,29.32 8.85,24.71 8.85,23.56 8.41,23.12 8.41,20.49 8.85,20.05 8.85,13.34 9.4,12.79 9.4,8.39 9.21,8.2 5.66,8.2 4.97,8.88 4.97,25.64 6,32.1 5.8,38.64 4.99,45.06 4.94,45.34 4.88,45.62 1.17,59.45 1.17,62.51 1.26,62.6 5.72,62.6 5.78,62.54 5.78,57.64 8.6,47.98 9.97,38.79
BST_5VB on BOTTOM: 7.26,74.22 8.41,74.22 8.63,73.99 8.63,73.03 8.94,72.72 8.95,72.72 9.36,72.31 9.77,72.31 9.86,72.23 9.86,71.6 9.81,71.56 8.92,71.56 8.88,71.6 8.88,72.03 8.2,72.71 8.2,73.55 8.04,73.71 7.29,73.71 7.2,73.8 7.2,74.15
CBN on TOP: 20.15,18.84 20.08,18.92 20.08,19.15 20.1,19.18 21.01,19.18 21.28,19.45 21.46,19.45 21.65,19.64 22.55,19.64 22.55,18.97 22.42,18.84
CBP on TOP: 20.1,19.73 20.91,19.73 21.41,20.23 22.51,20.23 22.55,20.27 22.55,21.02 21.21,21.02 20.08,19.9 20.08,19.75
LDO1_CAP on TOP: 20.13,16.38 20.89,16.38 22.06,15.21 23.11,15.21 23.57,14.75 23.57,13.43 23.55,13.4 23.04,13.4 23.02,13.42 23.02,14.07 22.83,14.26 22,14.26 20.09,16.17 20.09,16.34
LX_5VB on BOTTOM (solid shape): 12.71,79.86 12.71,79.26 12.7,79.26 12.7,78.76 13.18,78.29 14.56,78.29 14.83,78.01 14.83,75.15 14.39,74.71 8.77,74.71 8.45,74.39 6.1,74.39 5.97,74.52 5.97,74.71 6.04,74.77 7.69,74.77 7.94,75.02 7.94,76.55 7.95,76.56 7.95,76.96 10.96,79.96 12.61,79.96
MIC_CAP on TOP: 17.72,15.94 17.85,15.94 17.91,15.88 17.91,13.53 17.59,13.21 16.64,13.21 16.58,13.15 16.58,12.71 16.51,12.64 15.62,12.64 15.56,12.71 15.56,13.34 15.82,13.6 17.34,13.6 17.47,13.72 17.47,14.55 17.66,14.74 17.66,15.88
RING2 on BOTTOM: 28.37,35.76 25.76,35.76 25.68,35.68 25.68,35.1 25.77,35.01 28.29,35.01 28.42,35.14 28.42,35.7
RING2 on IN1: 25.89,34.55 25.74,34.7 25.74,35.29 26.02,35.57 28.21,35.57 28.37,35.41 28.37,34.63 28.28,34.55
RING2 on IN1: 16.67,13.62 15.7,13.62 15.55,13.77 15.55,14.81 16.49,15.75 21.21,15.75 21.34,15.63 21.34,14.87 21.21,14.74 17.02,14.74 16.74,14.46 16.74,13.7
RING2_R on BOTTOM: 21.86,36.96 22,36.83 22,35.92 22.2,35.71 25.38,35.71 25.43,35.66 25.43,35.05 25.36,34.97 21.71,34.97 20.97,35.71 20.51,35.71 20.38,35.84 20.38,36.78 20.57,36.96
RING2_R on IN2: 24.31,35.68 24.51,35.88 24.51,36.77 24.39,36.9 20.5,36.9 20.35,36.75 20.35,35.8 20.48,35.68
SLEEVE on BOTTOM: 26.04,29.91 25.71,30.24 25.71,31.18 25.7,31.19 25.7,31.77 25.7,31.77 25.7,31.99 25.78,32.07 27.12,32.07 27.12,30.11 26.93,29.91
SLEEVE on IN1: 26.24,31.36 27.05,31.36 27.14,31.27 27.14,28.61 26.99,28.45 26.23,28.45 26.1,28.58 26.1,31.23
SLEEVE on IN1: 20.84,14.62 20.84,14.62 22.35,14.62 22.48,14.48 22.48,13.79 22.04,13.35 17.01,13.35 16.85,13.51 16.85,14.51 16.96,14.62
SLEEVE_R on TOP: 23.75,33.53 23.75,32.52 23.56,32.33 22.8,32.33 21.02,34.11 18.55,34.11 18.42,34.23 18.42,35.25 18.61,35.44 21.85,35.44
SLEEVE_R on BOTTOM: 19.88,37.03 20.07,36.84 20.07,34.61 19.88,34.42 18.55,34.42 18.42,34.55 18.42,34.93 18.5,35.01 19.02,35.01 19.06,35.05 19.06,35.73 19.01,35.78 18.46,35.78 18.42,35.82 18.42,36.9 18.55,37.03
SLEEVE_R on BOTTOM: 26.36,32.33 26.29,32.26 23.24,32.26 23.12,32.39 23.12,33.53 23.31,33.72 26.1,33.72 26.36,33.47
SLEEVE_R on IN2: 18.43,36.86 19.18,36.86 20.25,35.8 20.25,35.68 19.63,35.06 19.5,35.06 18.76,35.8 18.43,35.8 18.31,35.92 18.31,36.73
SPK_-OUT-L+ on TOP: 18.23,5.21 18.1,5.34 18.1,6.38 18.21,6.48 19.18,6.48 19.24,6.42 19.24,5.28 19.18,5.21
SPK_-OUT-L+ on IN1: 17.4,20.84 17.02,21.22 17.02,21.47 18.14,22.58 18.14,23.51 18.25,23.63 18.86,23.63 18.93,23.56 18.93,22.26 17.5,20.84
SPK_-OUT-L+ on IN1: 18.23,5.21 18.1,5.34 18.1,6.48 19.18,6.48 19.24,6.42 19.24,5.28 19.18,5.21
SPK_-OUT-L- on TOP: 16.64,5.21 16.57,5.28 16.57,6.41 16.64,6.48 17.59,6.48 17.66,6.42 17.66,5.28 17.59,5.21
SPK_-OUT-L- on IN1: 16.64,5.21 16.51,5.34 16.51,6.48 17.59,6.48 17.66,6.42 17.66,5.28 17.59,5.21
SPK_-OUT-L- on IN1: 16.77,21.53 14.49,21.53 14.41,21.45 14.41,21.44 14.3,21.33 14.21,21.33 13.92,21.62 13.92,22.02 14.23,22.33 16.23,22.33 16.77,22.87 16.77,23.56 16.83,23.63 17.59,23.63 17.66,23.56 17.66,22.42
SPK_-OUT-R+ on TOP: 14.8,5.21 14.67,5.34 14.67,6.48 15.75,6.48 15.82,6.42 15.82,5.28 15.75,5.21
SPK_-OUT-R+ on IN2: 13.72,21.47 13.53,21.66 13.53,22.29 14.16,22.93 15.18,22.93 15.34,22.77 15.34,22.52 14.29,21.47
SPK_-OUT-R+ on IN2: 14.86,5.21 14.74,5.34 14.74,6.48 15.82,6.48 15.88,6.42 15.88,5.28 15.82,5.21
SPK_-OUT-R- on TOP: 13.15,5.21 13.02,5.34 13.02,6.42 13.08,6.48 14.1,6.48 14.16,6.42 14.16,5.28 14.1,5.21
SPK_-OUT-R- on IN2: 13.15,5.21 13.02,5.34 13.02,6.48 14.1,6.48 14.16,6.42 14.16,5.28 14.1,5.21
SPK_-OUT-R- on IN2: 15.69,22.61 15.18,23.12 15.05,23.12 15.05,23.82 15.12,23.88 16.51,23.88 16.64,23.76 16.64,22.74 16.51,22.61
SPK_L+ on TOP: 19.18,9.09 19.18,8.2 19.12,8.13 18.85,8.13 18.68,8.31 18.55,8.31 18.47,8.23 18.47,7.97 18.61,7.83 18.61,7.31 18.67,7.25 19.12,7.25 19.18,7.18 19.18,6.74 19.09,6.65 18.19,6.65 18.1,6.74 18.1,8.86 18.23,8.99 18.24,8.99 18.49,9.24 19.03,9.24
SPK_L+ on BOTTOM: 17.31,9.98 17.31,10.96 17.31,11.37 17.37,11.44 17.83,11.44 18.22,11.06 18.22,10.69 19.17,9.73 19.17,8.23 19.07,8.13 18.29,8.13 18.17,8.26 18.17,9.11
SPK_L- on TOP: 16.51,8.26 16.51,9.22 16.63,9.34 17.11,9.34 17.56,8.88 17.56,6.71 17.47,6.62 16.7,6.62 16.64,6.67 16.64,7.18 16.7,7.25 16.89,7.25 17.02,7.37 17.02,7.83 17.24,8.05 17.24,8.21 17.14,8.31 16.95,8.31 16.83,8.2 16.58,8.2
SPK_L- on BOTTOM: 16.42,8.2 16.31,8.31 16.31,11.36 16.39,11.44 16.95,11.44 17.01,11.37 17.01,9.64 17.34,9.31 17.34,8.26 17.28,8.2
SPK_R+ on TOP: 15.68,9.33 15.75,9.25 15.75,8.26 15.69,8.2 15.43,8.2 15.29,8.34 15.16,8.34 15.05,8.23 15.05,7.96 15.18,7.83 15.18,7.31 15.24,7.25 15.62,7.25 15.69,7.18 15.69,6.74 15.62,6.68 14.86,6.68 14.85,6.67 14.74,6.67 14.67,6.74 14.67,8.91 15.09,9.33
SPK_R+ on BOTTOM: 15.28,9.76 15.28,11.37 15.37,11.37 15.43,11.44 15.98,11.44 16.04,11.37 16.04,8.29 15.97,8.21 15.06,8.21 14.95,8.32 14.95,9.43
SPK_R- on TOP: 13.21,7.25 13.53,7.25 13.59,7.31 13.59,7.83 13.83,8.07 13.83,8.19 13.71,8.32 13.5,8.32 13.38,8.2 13.15,8.2 13.02,8.32 13.02,9.16 13.15,9.28 13.75,9.28 14.13,8.91 14.13,6.71 14.04,6.62 13.21,6.62 13.15,6.68 13.15,7.18
SPK_R- on BOTTOM: 14.03,8.2 13.03,8.2 12.94,8.29 12.94,9.95 14.3,11.31 14.43,11.44 14.87,11.44 14.94,11.37 14.94,9.98 14.09,9.13 14.09,8.26
N70877951 on TOP: 7.98,57.8 5.94,57.8 5.55,58.2 3.06,58.2 2.89,58.37 2.89,59.18 3.14,59.43 6.74,59.43 7.7,60.38 8.41,60.38 8.41,57.94 8.26,57.79 7.99,57.79
N71020818 on TOP (solid shape): 3.43,73.46 3.43,62.32 3.13,62.02 1.25,62.02 1.15,62.12 1.15,73.55 1.21,73.61 3.28,73.61
N71020818 on BOTTOM (solid shape): 5.88,74.2 6.61,74.2 6.67,74.14 6.67,73.75 6.54,73.63 3.75,73.63 3.37,73.25 3.37,61.63 3.24,61.5 1.34,61.5 1.21,61.63 1.21,71.09 1.85,71.72 1.85,73.44 1.59,73.69 1.59,74.39 1.72,74.52 5.57,74.52
N71020848 on BOTTOM (solid shape): 9.91,74.45 9.91,72.99 9.85,72.93 8.96,72.93 8.89,72.99 8.89,74.45 8.96,74.52 9.85,74.52
N71020994 on BOTTOM (solid shape): 14.67,79.64 15.5,79.64 15.56,79.57 15.56,78.56 15.5,78.49 13.4,78.49 13.34,78.56 13.34,79.95 13.4,80.02 14.29,80.02

Small or netless copper shapes (teardrops, artwork), in the pictures only: 4 on TOP, 5 on BOTTOM

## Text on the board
Ref Des/Silkscreen Bottom: M2X3L | S4 | S3
User.Comments: LS-H451P | 2019-06-21 | Peter | 2020-06-21 | EDW40 | 1.0(A00)
Ref Des/Silkscreen Top: HF | S2 | S1
User.39: GND4
User.40: GND5
User.41: FIGURE | SIZE | 8.0 | 28.0 | 91.0 | 71.0 | 43.0x24.0 | 51.0x24.0 | 71.0x31.0 | 79.0x31.0 | 98.0x79.0 | DRILL CHART: TOP to BOTTOM | ALL UNITS ARE IN MILS | TOLERANCE | +3.0/-3.0 | +2.0/-2.0 | PLATED | NON-PLATED | QTY | 547 | 18 | 3 | 1 | 5 | 4
User.42: 0_8mm-6L-180926 | 5.3 mil | 4 mil | 4.1/3.5 | 5.3/7.4 | 4/5.7 | L2 | L5 | L2/L5
